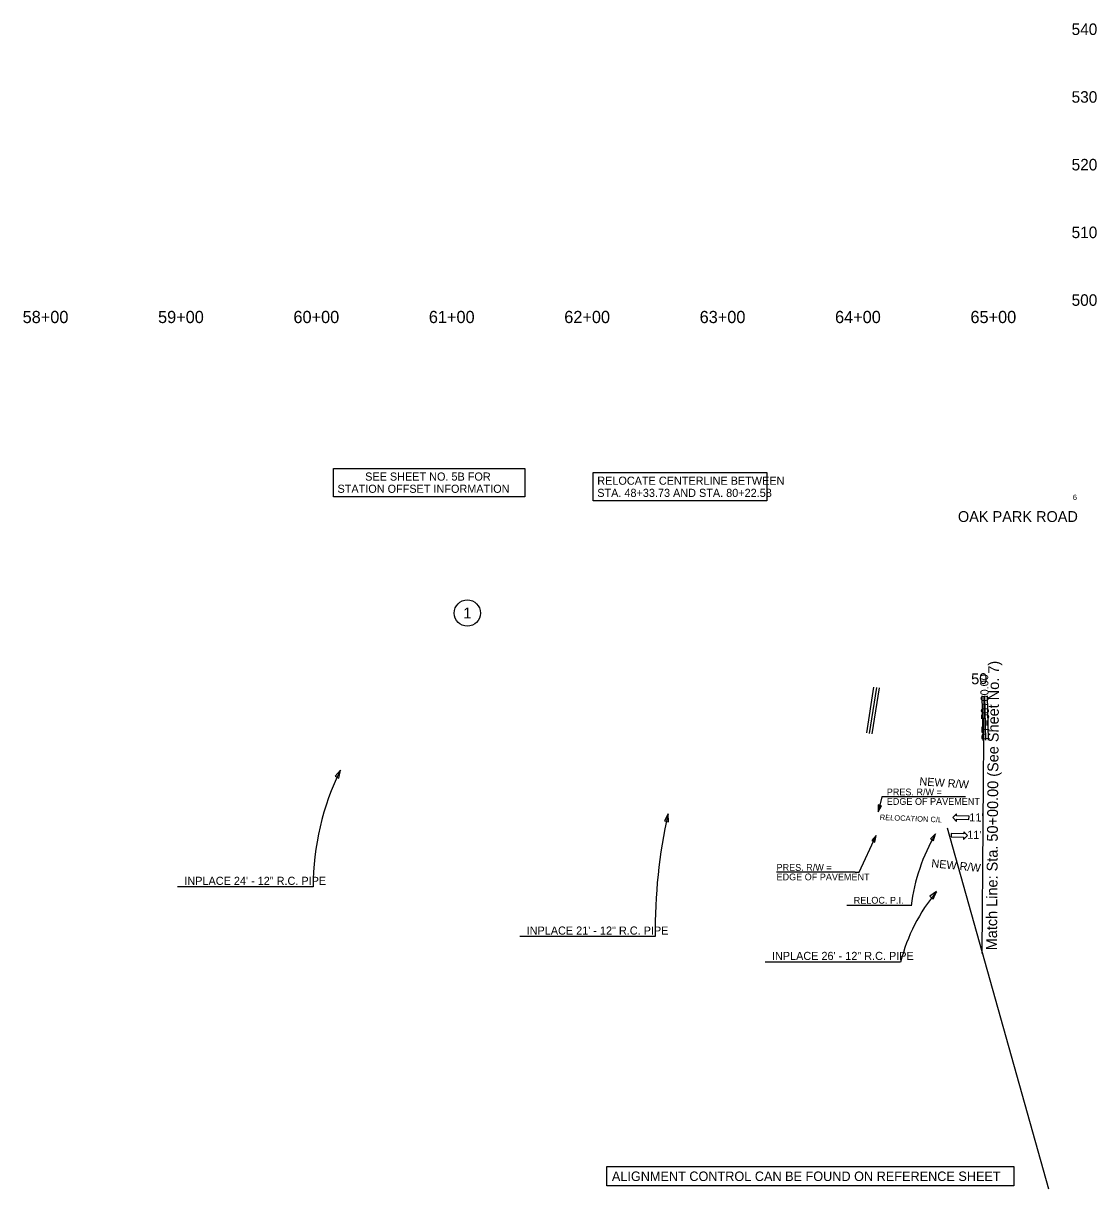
# Model space of a CAD drawing. Extents: x 1964377 to 1966966, y 1116414 to 1123213.
# Drawn here: x 1966157 to 1966950, y 1116925 to 1117785 of the extents above; entities that cross this region are included whole.
import ezdxf

# ---------------------------------------------------------------- set-up
doc = ezdxf.new("R2010")
doc.units = 0
for name, color, linetype in [('RD_DDB_Profile_Elev', 7, 'Continuous'), ('RD_DDB_StaTX', 7, 'Continuous'), ('RD_EX_DV_Prop', 7, 'Continuous'), ('RD_EX_DV_TX_Prop', 7, 'Continuous'), ('RD_EX_RW_TX', 7, 'Continuous'), ('RD_HC_Data', 7, 'Continuous'), ('RD_HC_Data_Rel', 7, 'Continuous'), ('RD_HC_TX_Sta50', 7, 'Continuous'), ('RD_PD_Final_LnLine', 7, 'Continuous'), ('RD_PD_Final_TX', 7, 'Continuous'), ('RD_PD_RW_TX', 7, 'Continuous'), ('RD_SHT_MatchLine', 7, 'Continuous'), ('RD_SHT_TX', 7, 'Continuous'), ('RD_Sketch1', 7, 'Continuous'), ('RD_TX_Drainage', 7, 'Continuous'), ('RD_TX_StaOff', 7, 'Continuous')]:
    doc.layers.add(name, color=color, linetype=linetype)

msp = doc.modelspace()

# ---------------------------------------------------------------- linework, layer by layer
at = {"layer": 'RD_EX_DV_Prop'}
msp.add_line((1966839.4, 1117191.4), (1966914.25, 1116924.8), dxfattribs=at)
at = {"layer": 'RD_EX_DV_TX_Prop'}
msp.add_circle((1966485.05, 1117349.92), 9.72, dxfattribs=at)
at = {"layer": 'RD_EX_RW_TX'}
for p, q in [((1966852.88, 1117214.27), (1966794.84, 1117214.27)), ((1966771.45, 1117158.54), (1966713.41, 1117158.54))]:
    msp.add_line(p, q, dxfattribs=at)
for points in [[(1966794.84, 1117214.27), (1966791.2, 1117214.27), (1966788.47, 1117203.18)], [(1966771.45, 1117158.54), (1966774.49, 1117158.54), (1966786.95, 1117185.73)]]:
    msp.add_lwpolyline(points, dxfattribs=at)
for points in [[(1966788.36, 1117208.18), (1966788.47, 1117203.18), (1966790.88, 1117207.56)], [(1966786.12, 1117180.8), (1966786.95, 1117185.73), (1966783.76, 1117181.88)]]:
    msp.add_lwpolyline(points, close=True, dxfattribs=at)
at = {"layer": 'RD_HC_Data'}
for p, q in [((1966780.17, 1117261.36), (1966785.38, 1117295.19)), ((1966782.15, 1117261.06), (1966787.36, 1117294.89)), ((1966784.12, 1117260.75), (1966789.33, 1117294.58)), ((1966865.99, 1117255.87), (1966865.23, 1117288.7)), ((1966867.99, 1117255.92), (1966867.23, 1117288.75)), ((1966869.99, 1117255.97), (1966869.23, 1117288.79))]:
    msp.add_line(p, q, dxfattribs=at)
at = {"layer": 'RD_HC_Data_Rel'}
msp.add_line((1966812.86, 1117133.81), (1966765.41, 1117133.81), dxfattribs=at)
for points in [[(1966578.01, 1117453.66), (1966706.33, 1117453.66), (1966706.33, 1117432.66), (1966578.01, 1117432.66)], [(1966829.45, 1117181.95), (1966830.77, 1117186.78), (1966827.22, 1117183.26)]]:
    msp.add_lwpolyline(points, close=True, dxfattribs=at)
msp.add_arc((1966951.23, 1117116.54), 139.44, 149.75441, 172.88691, dxfattribs=at)
at = {"layer": 'RD_PD_Final_LnLine'}
for points in [[(1966855.51, 1117197.48), (1966855.56, 1117199.88), (1966846.39, 1117200.08), (1966846.43, 1117201.7), (1966843.54, 1117198.94), (1966846.31, 1117196.05), (1966846.34, 1117197.68)], [(1966842.46, 1117186.99), (1966842.41, 1117184.59), (1966851.58, 1117184.4), (1966851.54, 1117182.77), (1966854.43, 1117185.54), (1966851.66, 1117188.43), (1966851.63, 1117186.8)]]:
    msp.add_lwpolyline(points, close=True, dxfattribs=at)
at = {"layer": 'RD_SHT_MatchLine'}
msp.add_lwpolyline([(1966865.17, 1117098.55), (1966865.9, 1117193.55), (1966866.64, 1117288.54)], dxfattribs=at)
at = {"layer": 'RD_Sketch1'}
msp.add_lwpolyline([(1966588.16, 1116941.19), (1966888.59, 1116941.19), (1966888.59, 1116926.93), (1966588.16, 1116926.93)], close=True, dxfattribs=at)
at = {"layer": 'RD_TX_Drainage'}
for p, q in [((1966371.1, 1117147.65), (1966271.06, 1117147.65)), ((1966623.89, 1117110.92), (1966523.86, 1117110.92)), ((1966805.06, 1117092.2), (1966705.03, 1117092.2))]:
    msp.add_line(p, q, dxfattribs=at)
for points in [[(1966390.14, 1117228.08), (1966391.31, 1117233.97), (1966387.35, 1117229.45)], [(1966633.58, 1117195.73), (1966633.35, 1117201.72), (1966630.55, 1117196.42)], [(1966829.05, 1117138.71), (1966831.59, 1117144.15), (1966826.67, 1117140.71)]]:
    msp.add_lwpolyline(points, close=True, dxfattribs=at)
for centre, radius, start, end in [((1966567.35, 1117147.22), 196.25, 153.76786, 179.87417), ((1967005.04, 1117117.12), 381.2, 167.17778, 180.93203), ((1966930.74, 1117060.77), 129.55, 139.9399, 165.95662)]:
    msp.add_arc(centre, radius, start, end, dxfattribs=at)
at = {"layer": 'RD_TX_StaOff'}
msp.add_lwpolyline([(1966386.08, 1117456.7), (1966527.63, 1117456.7), (1966527.63, 1117435.7), (1966386.08, 1117435.7)], close=True, dxfattribs=at)

# ---------------------------------------------------------------- texts
at = {"layer": 'RD_DDB_Profile_Elev'}
for s, p in [('540', (1966931.34, 1117776.8)), ('530', (1966931.34, 1117726.8)), ('520', (1966931.34, 1117676.8)), ('510', (1966931.34, 1117626.8)), ('500', (1966931.34, 1117576.8))]:
    msp.add_text(s, height=8.5, dxfattribs=at).set_placement(p)
at = {"layer": 'RD_DDB_StaTX'}
for s, p in [('58+00', (1966156.62, 1117564.05)), ('59+00', (1966256.62, 1117564.05)), ('60+00', (1966356.62, 1117564.05)), ('61+00', (1966456.62, 1117564.05)), ('62+00', (1966556.62, 1117564.05)), ('63+00', (1966656.62, 1117564.05)), ('64+00', (1966756.62, 1117564.05)), ('65+00', (1966856.62, 1117564.05))]:
    msp.add_text(s, height=9, dxfattribs=at).set_placement(p)
at = {"layer": 'RD_EX_DV_TX_Prop'}
msp.add_text('1', height=8, dxfattribs=at).set_placement((1966482.13, 1117345.93))
at = {"layer": 'RD_EX_RW_TX'}
for s, p in [('PRES. R/W = ', (1966794.84, 1117215.27)), ('EDGE OF PAVEMENT', (1966794.84, 1117208.27)), ('PRES. R/W = ', (1966713.42, 1117159.54)), ('EDGE OF PAVEMENT', (1966713.42, 1117152.54))]:
    msp.add_text(s, height=5, dxfattribs=at).set_placement(p)
at = {"layer": 'RD_HC_Data'}
msp.add_text('PT=50+00.00', height=6, rotation=91.33273, dxfattribs=at).set_placement((1966870.81, 1117256.18))
at = {"layer": 'RD_HC_Data_Rel'}
for s, height, p in [('RELOCATE CENTERLINE BETWEEN', 6, (1966581.01, 1117444.66)), ('STA. 48+33.73 AND STA. 80+22.58', 6, (1966581.01, 1117435.66)), ('RELOC. P.I.', 5, (1966770.41, 1117135.31))]:
    msp.add_text(s, height=height, dxfattribs=at).set_placement(p)
msp.add_text('RELOCATION C/L', height=4, rotation=357.61289, dxfattribs=at).set_placement((1966789.61, 1117197.14))
at = {"layer": 'RD_HC_TX_Sta50'}
msp.add_text('50', height=8, rotation=1.33274, dxfattribs=at).set_placement((1966857.25, 1117297.27))
at = {"layer": 'RD_PD_Final_TX'}
for p in [(1966855.77, 1117196.08), (1966854.16, 1117183.22)]:
    msp.add_text("11'", height=6, rotation=359.06797, dxfattribs=at).set_placement(p)
at = {"layer": 'RD_PD_RW_TX'}
for rotation, p in [(356.04425, (1966818.77, 1117222.75)), (354.31686, (1966827.56, 1117162.23))]:
    msp.add_text('NEW R/W', height=6, rotation=rotation, dxfattribs=at).set_placement(p)
at = {"layer": 'RD_SHT_MatchLine'}
msp.add_text('Match Line: Sta. 50+00.00 (See Sheet No. 7)', height=8, rotation=89.55533, dxfattribs=at).set_placement((1966876.19, 1117100.81))
at = {"layer": 'RD_SHT_TX'}
for s, height, p in [('6', 4, (1966932.23, 1117433.35)), ('OAK PARK ROAD', 8, (1966847.39, 1117417.18))]:
    msp.add_text(s, height=height, dxfattribs=at).set_placement(p)
at = {"layer": 'RD_Sketch1'}
msp.add_text('ALIGNMENT CONTROL CAN BE FOUND ON REFERENCE SHEET', height=7, dxfattribs=at).set_placement((1966591.81, 1116930.48))
at = {"layer": 'RD_TX_Drainage'}
for s, p in [('INPLACE 24\' - 12" R.C. PIPE', (1966276.06, 1117149.15)), ('INPLACE 21\' - 12" R.C. PIPE', (1966528.86, 1117112.42)), ('INPLACE 26\' - 12" R.C. PIPE', (1966710.03, 1117093.7))]:
    msp.add_text(s, height=6, dxfattribs=at).set_placement(p)
at = {"layer": 'RD_TX_StaOff'}
for s, p in [('SEE SHEET NO. 5B FOR', (1966409.58, 1117447.7)), ('STATION OFFSET INFORMATION', (1966389.17, 1117438.7))]:
    msp.add_text(s, height=6, dxfattribs=at).set_placement(p)

doc.saveas('drawing.dxf')
